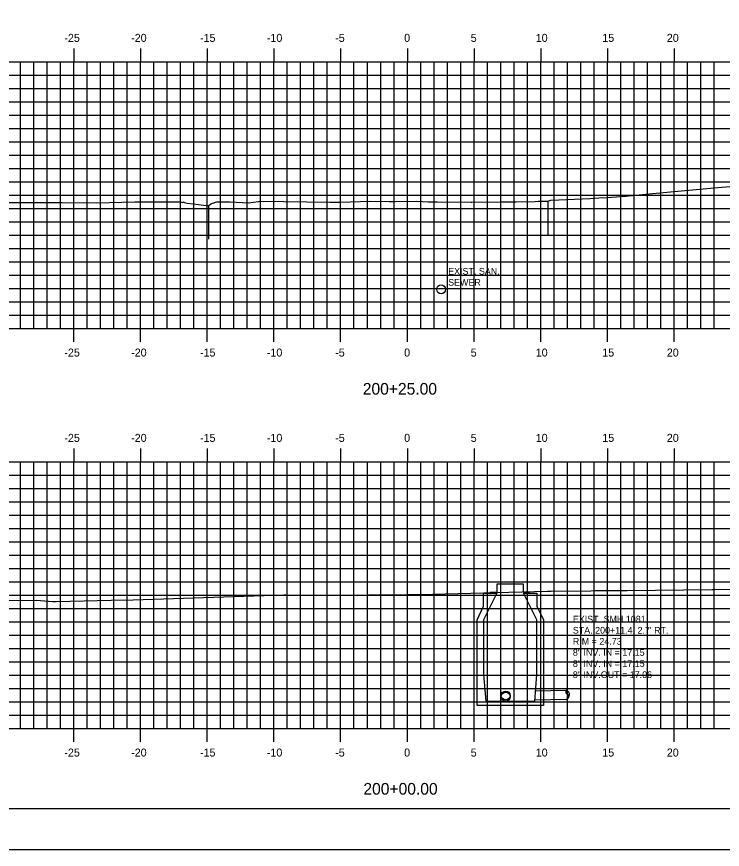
# Model space of a CAD drawing. Extents: x 1023237 to 1023407, y 394697 to 394807.
# Drawn here: x 1023290.4 to 1023343.3, y 394696.5 to 394759 of the extents above; entities that cross this region are included whole.
import ezdxf

# ---------------------------------------------------------------- set-up
doc = ezdxf.new("R2010")
doc.units = 0
for name, color, linetype in [('BORDER', 7, 'Continuous'), ('D_Roadway_Centerline', 7, 'Continuous'), ('D_Text_Monospaced', 7, 'Continuous'), ('H_V ANNOTATION', 7, 'Continuous'), ('MAJOR', 7, 'Continuous'), ('MINOR', 7, 'Continuous'), ('PLOT BOUNDARY', 7, 'Continuous'), ('S_Drainage_MH', 7, 'Continuous'), ('S_Roadway_Centerline', 7, 'Continuous'), ('S_Roadway_Edge_Pavement', 7, 'Continuous'), ('S_Utilities_UG_Sanitary_Sewer', 7, 'Continuous')]:
    doc.layers.add(name, color=color, linetype=linetype)

msp = doc.modelspace()

# ---------------------------------------------------------------- linework, layer by layer
at = {"layer": 'BORDER'}
msp.add_line((1023244.664, 394699.607), (1023404.664, 394699.607), dxfattribs=at)
at = {"layer": 'MAJOR'}
for p, q in [((1023294.663, 394756.609), (1023294.663, 394755.607)), ((1023299.663, 394756.609), (1023299.663, 394755.607)), ((1023304.663, 394756.609), (1023304.663, 394755.607)), ((1023309.663, 394756.609), (1023309.663, 394755.607)), ((1023314.663, 394756.609), (1023314.663, 394755.607)), ((1023319.663, 394756.609), (1023319.663, 394755.607)), ((1023324.663, 394756.609), (1023324.663, 394755.607)), ((1023329.663, 394756.609), (1023329.663, 394755.607)), ((1023334.663, 394756.609), (1023334.663, 394755.607)), ((1023339.663, 394756.609), (1023339.663, 394755.607)), ((1023249.663, 394755.607), (1023389.663, 394755.607)), ((1023294.663, 394735.607), (1023294.663, 394755.607)), ((1023299.663, 394735.607), (1023299.663, 394755.607)), ((1023304.663, 394735.607), (1023304.663, 394755.607)), ((1023309.663, 394735.607), (1023309.663, 394755.607)), ((1023314.663, 394735.607), (1023314.663, 394755.607)), ((1023319.663, 394735.607), (1023319.663, 394755.607)), ((1023324.663, 394735.607), (1023324.663, 394755.607)), ((1023329.663, 394735.607), (1023329.663, 394755.607)), ((1023334.663, 394735.607), (1023334.663, 394755.607)), ((1023339.663, 394735.607), (1023339.663, 394755.607)), ((1023249.663, 394750.607), (1023389.663, 394750.607)), ((1023249.663, 394745.607), (1023389.663, 394745.607)), ((1023249.663, 394740.607), (1023389.663, 394740.607)), ((1023249.663, 394735.607), (1023389.663, 394735.607)), ((1023294.663, 394734.605), (1023294.663, 394735.607)), ((1023299.663, 394734.605), (1023299.663, 394735.607)), ((1023304.663, 394734.605), (1023304.663, 394735.607)), ((1023309.663, 394734.605), (1023309.663, 394735.607)), ((1023314.663, 394734.605), (1023314.663, 394735.607)), ((1023319.663, 394734.605), (1023319.663, 394735.607)), ((1023324.663, 394734.605), (1023324.663, 394735.607)), ((1023329.663, 394734.605), (1023329.663, 394735.607)), ((1023334.663, 394734.605), (1023334.663, 394735.607)), ((1023339.663, 394734.605), (1023339.663, 394735.607)), ((1023294.663, 394726.609), (1023294.663, 394725.607)), ((1023299.663, 394726.609), (1023299.663, 394725.607)), ((1023304.663, 394726.609), (1023304.663, 394725.607)), ((1023309.663, 394726.609), (1023309.663, 394725.607)), ((1023314.663, 394726.609), (1023314.663, 394725.607)), ((1023319.663, 394726.609), (1023319.663, 394725.607)), ((1023324.663, 394726.609), (1023324.663, 394725.607)), ((1023329.663, 394726.609), (1023329.663, 394725.607)), ((1023334.663, 394726.609), (1023334.663, 394725.607)), ((1023339.663, 394726.609), (1023339.663, 394725.607)), ((1023249.663, 394725.607), (1023389.663, 394725.607)), ((1023294.663, 394705.607), (1023294.663, 394725.607)), ((1023299.663, 394705.607), (1023299.663, 394725.607)), ((1023304.663, 394705.607), (1023304.663, 394725.607)), ((1023309.663, 394705.607), (1023309.663, 394725.607)), ((1023314.663, 394705.607), (1023314.663, 394725.607)), ((1023319.663, 394705.607), (1023319.663, 394725.607)), ((1023324.663, 394705.607), (1023324.663, 394725.607)), ((1023329.663, 394705.607), (1023329.663, 394725.607)), ((1023334.663, 394705.607), (1023334.663, 394725.607)), ((1023339.663, 394705.607), (1023339.663, 394725.607)), ((1023249.663, 394720.607), (1023389.663, 394720.607)), ((1023249.663, 394715.607), (1023389.663, 394715.607)), ((1023249.663, 394710.607), (1023389.663, 394710.607)), ((1023249.663, 394705.607), (1023389.663, 394705.607)), ((1023294.663, 394704.605), (1023294.663, 394705.607)), ((1023299.663, 394704.605), (1023299.663, 394705.607)), ((1023304.663, 394704.605), (1023304.663, 394705.607)), ((1023309.663, 394704.605), (1023309.663, 394705.607)), ((1023314.663, 394704.605), (1023314.663, 394705.607)), ((1023319.663, 394704.605), (1023319.663, 394705.607)), ((1023324.663, 394704.605), (1023324.663, 394705.607)), ((1023329.663, 394704.605), (1023329.663, 394705.607)), ((1023334.663, 394704.605), (1023334.663, 394705.607)), ((1023339.663, 394704.605), (1023339.663, 394705.607))]:
    msp.add_line(p, q, dxfattribs=at)
at = {"layer": 'MINOR'}
for p, q in [((1023290.663, 394735.607), (1023290.663, 394755.607)), ((1023291.663, 394735.607), (1023291.663, 394755.607)), ((1023292.663, 394735.607), (1023292.663, 394755.607)), ((1023293.663, 394735.607), (1023293.663, 394755.607)), ((1023295.663, 394735.607), (1023295.663, 394755.607)), ((1023296.663, 394735.607), (1023296.663, 394755.607)), ((1023297.663, 394735.607), (1023297.663, 394755.607)), ((1023298.663, 394735.607), (1023298.663, 394755.607)), ((1023300.663, 394735.607), (1023300.663, 394755.607)), ((1023301.663, 394735.607), (1023301.663, 394755.607)), ((1023302.663, 394735.607), (1023302.663, 394755.607)), ((1023303.663, 394735.607), (1023303.663, 394755.607)), ((1023305.663, 394735.607), (1023305.663, 394755.607)), ((1023306.663, 394735.607), (1023306.663, 394755.607)), ((1023307.663, 394735.607), (1023307.663, 394755.607)), ((1023308.663, 394735.607), (1023308.663, 394755.607)), ((1023310.663, 394735.607), (1023310.663, 394755.607)), ((1023311.663, 394735.607), (1023311.663, 394755.607)), ((1023312.663, 394735.607), (1023312.663, 394755.607)), ((1023313.663, 394735.607), (1023313.663, 394755.607)), ((1023315.663, 394735.607), (1023315.663, 394755.607)), ((1023316.663, 394735.607), (1023316.663, 394755.607)), ((1023317.663, 394735.607), (1023317.663, 394755.607)), ((1023318.663, 394735.607), (1023318.663, 394755.607)), ((1023320.663, 394735.607), (1023320.663, 394755.607)), ((1023321.663, 394735.607), (1023321.663, 394755.607)), ((1023322.663, 394735.607), (1023322.663, 394755.607)), ((1023323.663, 394735.607), (1023323.663, 394755.607)), ((1023325.663, 394735.607), (1023325.663, 394755.607)), ((1023326.663, 394735.607), (1023326.663, 394755.607)), ((1023327.663, 394735.607), (1023327.663, 394755.607)), ((1023328.663, 394735.607), (1023328.663, 394755.607)), ((1023330.663, 394735.607), (1023330.663, 394755.607)), ((1023331.663, 394735.607), (1023331.663, 394755.607)), ((1023332.663, 394735.607), (1023332.663, 394755.607)), ((1023333.663, 394735.607), (1023333.663, 394755.607)), ((1023335.663, 394735.607), (1023335.663, 394755.607)), ((1023336.663, 394735.607), (1023336.663, 394755.607)), ((1023337.663, 394735.607), (1023337.663, 394755.607)), ((1023338.663, 394735.607), (1023338.663, 394755.607)), ((1023340.663, 394735.607), (1023340.663, 394755.607)), ((1023341.663, 394735.607), (1023341.663, 394755.607)), ((1023342.663, 394735.607), (1023342.663, 394755.607)), ((1023249.663, 394754.607), (1023389.663, 394754.607)), ((1023249.663, 394753.607), (1023389.663, 394753.607)), ((1023249.663, 394752.607), (1023389.663, 394752.607)), ((1023249.663, 394751.607), (1023389.663, 394751.607)), ((1023249.663, 394749.607), (1023389.663, 394749.607)), ((1023249.663, 394748.607), (1023389.663, 394748.607)), ((1023249.663, 394747.607), (1023389.663, 394747.607)), ((1023249.663, 394746.607), (1023389.663, 394746.607)), ((1023249.663, 394744.607), (1023389.663, 394744.607)), ((1023249.663, 394743.607), (1023389.663, 394743.607)), ((1023249.663, 394742.607), (1023389.663, 394742.607)), ((1023249.663, 394741.607), (1023389.663, 394741.607)), ((1023249.663, 394739.607), (1023389.663, 394739.607)), ((1023249.663, 394738.607), (1023389.663, 394738.607)), ((1023249.663, 394737.607), (1023389.663, 394737.607)), ((1023249.663, 394736.607), (1023389.663, 394736.607)), ((1023290.663, 394705.607), (1023290.663, 394725.607)), ((1023291.663, 394705.607), (1023291.663, 394725.607)), ((1023292.663, 394705.607), (1023292.663, 394725.607)), ((1023293.663, 394705.607), (1023293.663, 394725.607)), ((1023295.663, 394705.607), (1023295.663, 394725.607)), ((1023296.663, 394705.607), (1023296.663, 394725.607)), ((1023297.663, 394705.607), (1023297.663, 394725.607)), ((1023298.663, 394705.607), (1023298.663, 394725.607)), ((1023300.663, 394705.607), (1023300.663, 394725.607)), ((1023301.663, 394705.607), (1023301.663, 394725.607)), ((1023302.663, 394705.607), (1023302.663, 394725.607)), ((1023303.663, 394705.607), (1023303.663, 394725.607)), ((1023305.663, 394705.607), (1023305.663, 394725.607)), ((1023306.663, 394705.607), (1023306.663, 394725.607)), ((1023307.663, 394705.607), (1023307.663, 394725.607)), ((1023308.663, 394705.607), (1023308.663, 394725.607)), ((1023310.663, 394705.607), (1023310.663, 394725.607)), ((1023311.663, 394705.607), (1023311.663, 394725.607)), ((1023312.663, 394705.607), (1023312.663, 394725.607)), ((1023313.663, 394705.607), (1023313.663, 394725.607)), ((1023315.663, 394705.607), (1023315.663, 394725.607)), ((1023316.663, 394705.607), (1023316.663, 394725.607)), ((1023317.663, 394705.607), (1023317.663, 394725.607)), ((1023318.663, 394705.607), (1023318.663, 394725.607)), ((1023320.663, 394705.607), (1023320.663, 394725.607)), ((1023321.663, 394705.607), (1023321.663, 394725.607)), ((1023322.663, 394705.607), (1023322.663, 394725.607)), ((1023323.663, 394705.607), (1023323.663, 394725.607)), ((1023325.663, 394705.607), (1023325.663, 394725.607)), ((1023326.663, 394705.607), (1023326.663, 394725.607)), ((1023327.663, 394705.607), (1023327.663, 394725.607)), ((1023328.663, 394705.607), (1023328.663, 394725.607)), ((1023330.663, 394705.607), (1023330.663, 394725.607)), ((1023331.663, 394705.607), (1023331.663, 394725.607)), ((1023332.663, 394705.607), (1023332.663, 394725.607)), ((1023333.663, 394705.607), (1023333.663, 394725.607)), ((1023335.663, 394705.607), (1023335.663, 394725.607)), ((1023336.663, 394705.607), (1023336.663, 394725.607)), ((1023337.663, 394705.607), (1023337.663, 394725.607)), ((1023338.663, 394705.607), (1023338.663, 394725.607)), ((1023340.663, 394705.607), (1023340.663, 394725.607)), ((1023341.663, 394705.607), (1023341.663, 394725.607)), ((1023342.663, 394705.607), (1023342.663, 394725.607)), ((1023249.663, 394724.607), (1023389.663, 394724.607)), ((1023249.663, 394723.607), (1023389.663, 394723.607)), ((1023249.663, 394722.607), (1023389.663, 394722.607)), ((1023249.663, 394721.607), (1023389.663, 394721.607)), ((1023249.663, 394719.607), (1023389.663, 394719.607)), ((1023249.663, 394718.607), (1023389.663, 394718.607)), ((1023249.663, 394717.607), (1023389.663, 394717.607)), ((1023249.663, 394716.607), (1023389.663, 394716.607)), ((1023249.663, 394714.607), (1023389.663, 394714.607)), ((1023249.663, 394713.607), (1023389.663, 394713.607)), ((1023249.663, 394712.607), (1023389.663, 394712.607)), ((1023249.663, 394711.607), (1023389.663, 394711.607)), ((1023249.663, 394709.607), (1023389.663, 394709.607)), ((1023249.663, 394708.607), (1023389.663, 394708.607)), ((1023249.663, 394707.607), (1023389.663, 394707.607)), ((1023249.663, 394706.607), (1023389.663, 394706.607))]:
    msp.add_line(p, q, dxfattribs=at)
at = {"layer": 'PLOT BOUNDARY'}
msp.add_lwpolyline([(1023236.57, 394696.548), (1023406.57, 394696.548), (1023406.57, 394806.548), (1023236.57, 394806.548)], close=True, dxfattribs=at)
at = {"layer": 'S_Drainage_MH'}
for p, q in [((1023325.378, 394715.767), (1023326.363, 394715.767)), ((1023326.363, 394715.767), (1023325.378, 394713.765)), ((1023325.378, 394714.782), (1023325.378, 394715.767)), ((1023329.381, 394713.765), (1023328.364, 394715.767)), ((1023328.364, 394715.767), (1023329.381, 394715.767)), ((1023329.381, 394715.767), (1023329.381, 394714.782)), ((1023324.886, 394713.765), (1023325.378, 394714.782)), ((1023329.381, 394714.782), (1023329.873, 394713.765)), ((1023324.886, 394707.339), (1023324.886, 394713.765)), ((1023325.378, 394713.765), (1023325.378, 394709.668)), ((1023329.381, 394709.668), (1023329.381, 394713.765)), ((1023329.873, 394713.765), (1023329.873, 394707.339)), ((1023325.378, 394709.668), (1023325.543, 394707.667)), ((1023329.217, 394707.667), (1023329.381, 394709.668)), ((1023325.543, 394707.667), (1023329.217, 394707.667)), ((1023329.873, 394707.339), (1023324.886, 394707.339))]:
    msp.add_line(p, q, dxfattribs=at)
msp.add_lwpolyline([(1023328.856, 394715.808), (1023328.364, 394715.808), (1023328.364, 394716.432), (1023326.363, 394716.432), (1023326.363, 394715.808), (1023325.871, 394715.808)], dxfattribs=at)
at = {"layer": 'S_Roadway_Centerline'}
for points in [[(1023289.211, 394745.057), (1023293.156, 394745.049), (1023293.777, 394745.067), (1023296.337, 394745.041), (1023299.222, 394745.11), (1023300.896, 394745.119), (1023300.97, 394745.118), (1023302.261, 394745.103), (1023302.572, 394745.109), (1023302.678, 394745.08), (1023302.746, 394745.074), (1023302.833, 394745.064), (1023302.922, 394745.118), (1023302.957, 394745.05), (1023303.167, 394745.023), (1023303.636, 394744.959), (1023304.755, 394744.801), (1023304.938, 394744.957), (1023305.389, 394745.111), (1023305.988, 394745.119), (1023306.376, 394745.113), (1023307.754, 394745.037), (1023308.506, 394745.135), (1023308.528, 394745.138), (1023308.546, 394745.145), (1023308.551, 394745.148), (1023308.594, 394745.156), (1023308.638, 394745.156), (1023313.876, 394745.09), (1023314.483, 394745.091), (1023314.636, 394745.091), (1023316.884, 394745.166), (1023318.304, 394745.147), (1023318.504, 394745.146), (1023318.758, 394745.142), (1023320.362, 394745.152), (1023321.217, 394745.11), (1023321.494, 394745.11), (1023321.663, 394745.11), (1023321.926, 394745.111), (1023324.449, 394745.096), (1023324.486, 394745.096), (1023326.638, 394745.117), (1023327.02, 394745.121), (1023327.826, 394745.11), (1023329.235, 394745.142), (1023329.464, 394745.149), (1023329.51, 394745.149), (1023329.967, 394745.16), (1023330.187, 394745.166), (1023330.202, 394745.165), (1023330.419, 394745.24), (1023333.363, 394745.371), (1023334.01, 394745.402), (1023334.621, 394745.431), (1023335.701, 394745.508), (1023336.081, 394745.544), (1023336.241, 394745.56), (1023336.453, 394745.579), (1023336.54, 394745.587), (1023338.053, 394745.727), (1023342.935, 394746.177), (1023344.483, 394746.319)], [(1023289.236, 394715.208), (1023291.86, 394715.245), (1023293.069, 394715.14), (1023293.327, 394715.145), (1023297.458, 394715.226), (1023299.1, 394715.258), (1023310.43, 394715.624), (1023310.557, 394715.628), (1023315.915, 394715.588), (1023315.962, 394715.602), (1023316.745, 394715.634), (1023318.902, 394715.639), (1023319.466, 394715.643), (1023319.668, 394715.649), (1023320.6, 394715.663), (1023330.153, 394715.913), (1023330.458, 394715.917), (1023333.409, 394715.948), (1023333.756, 394715.952), (1023336.151, 394715.973), (1023342.513, 394716.036), (1023342.724, 394716.038), (1023345.005, 394716.062)]]:
    msp.add_lwpolyline(points, dxfattribs=at)
at = {"layer": 'S_Roadway_Edge_Pavement'}
for p, q in [((1023330.202, 394745.165), (1023330.202, 394742.665)), ((1023304.755, 394744.801), (1023304.755, 394742.301))]:
    msp.add_line(p, q, dxfattribs=at)
at = {"layer": 'S_Utilities_UG_Sanitary_Sewer'}
for p, q in [((1023329.279, 394708.425), (1023331.572, 394708.477)), ((1023329.224, 394707.757), (1023331.587, 394707.81))]:
    msp.add_line(p, q, dxfattribs=at)
for centre in [(1023322.195, 394738.55), (1023327.04, 394708.09), (1023327.04, 394708)]:
    msp.add_circle(centre, 0.333, dxfattribs=at)
for centre, radius, start, end in [((1023331.717, 394708.371), 0.18, 143.87953, 247.36442), ((1023331.491, 394708.159), 0.327, 327.64074, 75.63016), ((1023331.562, 394708.016), 0.207, 276.88484, 65.5777)]:
    msp.add_arc(centre, radius, start, end, dxfattribs=at)

# ---------------------------------------------------------------- texts
at = {"layer": 'D_Roadway_Centerline'}
for s, p in [('C', (1023319.658, 394745.897)), ('L', (1023319.663, 394745.89)), ('C', (1023319.658, 394716.372)), ('L', (1023319.663, 394716.365))]:
    msp.add_text(s, height=0.0146, dxfattribs=at).set_placement(p)
at = {"layer": 'D_Text_Monospaced'}
for s, height, p in [('EXIST. SAN.', 0.49998, (1023322.722, 394739.654)), ('SEWER', 0.5, (1023322.722, 394738.82)), ('EXIST. SMH 1081', 0.49998, (1023332.07, 394713.563)), ("STA. 200+11.4, 2.7' RT.", 0.49998, (1023332.07, 394712.73)), ('RIM = 24.73', 0.49998, (1023332.07, 394711.896)), ('8" INV. IN = 17.15', 0.49998, (1023332.07, 394711.063)), ('8" INV. IN = 17.15', 0.49998, (1023332.07, 394710.23)), ('8" INV.OUT = 17.06', 0.49998, (1023332.07, 394709.397))]:
    msp.add_text(s, height=height, dxfattribs=at).set_placement(p)
at = {"layer": 'H_V ANNOTATION'}
for s, height, p in [('-25', 0.6, (1023293.949, 394757.107)), ('-20', 0.6, (1023298.957, 394757.107)), ('-15', 0.6, (1023304.12, 394757.107)), ('-10', 0.6, (1023309.128, 394757.107)), ('-5', 0.6, (1023314.254, 394757.107)), ('0', 0.6, (1023319.422, 394757.107)), ('5', 0.6, (1023324.414, 394757.107)), ('10', 0.6, (1023329.289, 394757.107)), ('15', 0.6, (1023334.281, 394757.107)), ('20', 0.6, (1023339.117, 394757.107)), ('-25', 0.6, (1023293.949, 394733.507)), ('-20', 0.6, (1023298.957, 394733.507)), ('-15', 0.6, (1023304.12, 394733.507)), ('-10', 0.6, (1023309.128, 394733.507)), ('-5', 0.6, (1023314.254, 394733.507)), ('0', 0.6, (1023319.422, 394733.507)), ('5', 0.6, (1023324.414, 394733.507)), ('10', 0.6, (1023329.289, 394733.507)), ('15', 0.6, (1023334.281, 394733.507)), ('20', 0.6, (1023339.117, 394733.507)), ('200+25.00', 0.875, (1023316.323, 394730.65)), ('-25', 0.6, (1023293.949, 394727.107)), ('-20', 0.6, (1023298.957, 394727.107)), ('-15', 0.6, (1023304.12, 394727.107)), ('-10', 0.6, (1023309.128, 394727.107)), ('-5', 0.6, (1023314.254, 394727.107)), ('0', 0.6, (1023319.422, 394727.107)), ('5', 0.6, (1023324.414, 394727.107)), ('10', 0.6, (1023329.289, 394727.107)), ('15', 0.6, (1023334.281, 394727.107)), ('20', 0.6, (1023339.117, 394727.107)), ('-25', 0.6, (1023293.949, 394703.507)), ('-20', 0.6, (1023298.957, 394703.507)), ('-15', 0.6, (1023304.12, 394703.507)), ('-10', 0.6, (1023309.128, 394703.507)), ('-5', 0.6, (1023314.254, 394703.507)), ('0', 0.6, (1023319.422, 394703.507)), ('5', 0.6, (1023324.414, 394703.507)), ('10', 0.6, (1023329.289, 394703.507)), ('15', 0.6, (1023334.281, 394703.507)), ('20', 0.6, (1023339.117, 394703.507)), ('200+00.00', 0.875, (1023316.37, 394700.65))]:
    msp.add_text(s, height=height, dxfattribs=at).set_placement(p)
at = {"layer": 'S_Roadway_Centerline'}
for s, p in [('L', (1023315.907, 394715.709)), ('C', (1023315.91, 394715.717))]:
    msp.add_text(s, height=0.0146, dxfattribs=at).set_placement(p)

doc.saveas('drawing.dxf')
